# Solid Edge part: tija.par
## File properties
Author: user
Template: Normal.par
Last saved by: user
Revision: 4
Application: Solid Edge
Density: 7800.000 kg/m^3
Accuracy: 0.010
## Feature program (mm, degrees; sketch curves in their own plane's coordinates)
sketch for "unnamed Protrusion 1" plane through (0, 0, 0) normal (0, -1, 0) x-axis (1, 0, 0)
  line (-80, -4) -> (80, -4)
  line (80, -4) -> (80, 4)
  line (80, 4) -> (-80, 4)
  line (-80, 4) -> (-80, -4)
extrude "unnamed Protrusion 1" add finite 2 along +normal
sketch for "unnamed Cutout 1" plane through (0, -2, 0) normal (0, -1, 0) x-axis (1, 0, 0)
  line (-68, -1.5) -> (62, -1.5)
  line (62, -1.5) -> (62, 1.5)
  line (62, 1.5) -> (-68, 1.5)
  line (-68, 1.5) -> (-68, -1.5)
  dimension (linear) = 62
extrude "unnamed Cutout 1" cut through along -normal
sketch for "unnamed Cutout 2" plane through (0, -2, 0) normal (0, -1, 0) x-axis (1, 0, 0)
  circle centre (77, 0) radius 1.5
  dimension (linear) = 77
extrude "unnamed Cutout 2" cut through along -normal
mirror "unnamed Mirror 1" of "unnamed Cutout 2" about plane through (0, 0, 0) normal (1, 0, 0)
extrude "unnamed Cutout 3" cut through
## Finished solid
Body 1: solid body, 12 faces, 28 edges, 16 vertices.
  Faces by surface: plane 10, cylinder 2
  Edges by curve: line 24, circle 4
Bounding box of the edges (mm): 160.000 x 2.000 x 8.000, from (-80, -2, -4) to (80, 0, 4).
Cylindrical faces by radius (mm): R1.5 x2
Planar faces by outward normal: +x 2, +y 1, +z 2, -x 2, -y 1, -z 2
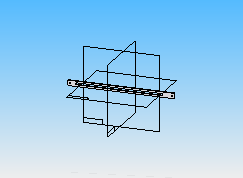
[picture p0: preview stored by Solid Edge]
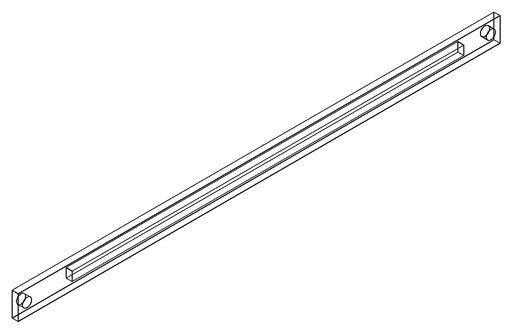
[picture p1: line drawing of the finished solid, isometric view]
